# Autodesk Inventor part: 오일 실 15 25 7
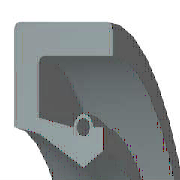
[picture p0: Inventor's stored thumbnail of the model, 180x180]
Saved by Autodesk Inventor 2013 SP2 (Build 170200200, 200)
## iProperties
Created: 2012-02
Part Number: 오일 실 15 25 7
Material: 고무
Description: 오일-실
Document SubType Name: Modeling
Standard: KS B 2804
Designer: mduedu
Standards Organization: KS
Language: ko-KR
Size Designation: S - 15 25 7
Categories: <MemberInstance><Categories><Category DisplayName="샤프트 부품" InternalName="7f7aeb1f-a693-4053-b835-cee3144e0d98" Mnemonic="SHFT"><Category DisplayName="실링" Intern
Density: 0.93 g/cm^3
IsCustomPart: 1
Author: mduedu
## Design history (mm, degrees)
revolve "본체" stored, may be unused: angle "d17" = 90 deg
revolve "스프링1" stored, may be unused: angle "d18" = 90 deg
body "Solid1"
sketch "스케치1"
  geometry: L1 (0, 12.5)-(7, 12.5); L2 (7, 12.5)-(7, 11.25); L3 (7, 11.25)-(1.75, 11.25); L4 (0, 12.5)-(0, 9.6); L5 (0, 9.6)-(1.75, 9.25); L6 (1.75, 9.25)-(4.9, 7.5); L7 (4.9, 7.5)-(0, 7.5); L8 (6.3, 8.375)-(6.3, 9.6); L9 (0, 0)-(9.586, 0) reference; L10 (4.9, 7.5)-(6.3, 8.375); L11 (0, 18)-(0, -3) reference; L12 (-1.917, 0)-(11.503, 0) reference; L13 (4.2, 9.6)-(1.75, 10.09); L14 (1.75, 10.09)-(1.75, 11.25); L15 (6.3, 9.6)-(5.6, 9.6); C1 r 0.455 at (4.9, 9.6); A1 r 0.7 centre (4.9, 9.6) between (5.6, 9.6) and (4.2, 9.6)
  constraints: 26 end point, 5 horizontal alignment, 4 perpendicular, 2 centre point, 2 collinear, 2 horizontal, 2 parallel, 2 point on circle, 2 point on line, 2 vertical alignment, 1 coincident
  dimensions: "d0" = 25 diameter of L1 L9 (= SD2); "d1" = 16.75 diameter of L8.start L9 (= ABDM); "d2" = 1.25 distance of L1.end L2.end (computed from SD); "d3" = 0.91 diameter of C1 (= SPDI); "d4" = 1.4 diameter of A1 (= SPDA); "d5" = 15 diameter of L6.end L9 (= NND); "d6" = 18.5 diameter of L5.end L9 (= TKDM); "d7" = 19.2 diameter of L4.end L9 (= HLDM); "d8" = 4.9 distance from line of C1.centre L4 (= SPDST); "d9" = 6.3 distance between parallel lines of L8 L4 (= SDI); "d10" = 7 distance between parallel lines of L2 L4 (= SWDT); "d12" = 1.75 distance between parallel lines of L14 L4 (= SD)
fillet "모깎기1" dims "d11" = 0.3 (= RR)
other parameters: "SD2" = 25 [user parameter; used in 1 equation term], "SWDT" = 7 [user parameter; used in 1 equation term], "RR" = 0.3 [user parameter; used in 1 equation term], "SD" = 1.75 [user parameter; used in 2 equation terms], "NND" = 15 [user parameter; used in 1 equation term], "SPDA" = 1.4 [user parameter; used in 1 equation term], "SPDI" = 0.91 [user parameter; used in 1 equation term], "TKDM" = 18.5 [user parameter; used in 1 equation term], "HLDM" = 19.2 [user parameter; used in 1 equation term], "ABDM" = 16.75 [user parameter; used in 1 equation term], "SDI" = 6.3 [user parameter; used in 1 equation term], "SPDST" = 4.9 [user parameter; used in 1 equation term], "d13" = 0, "d14" = 0, "d15" = 0, "LAB" = 0.35 [user parameter]
